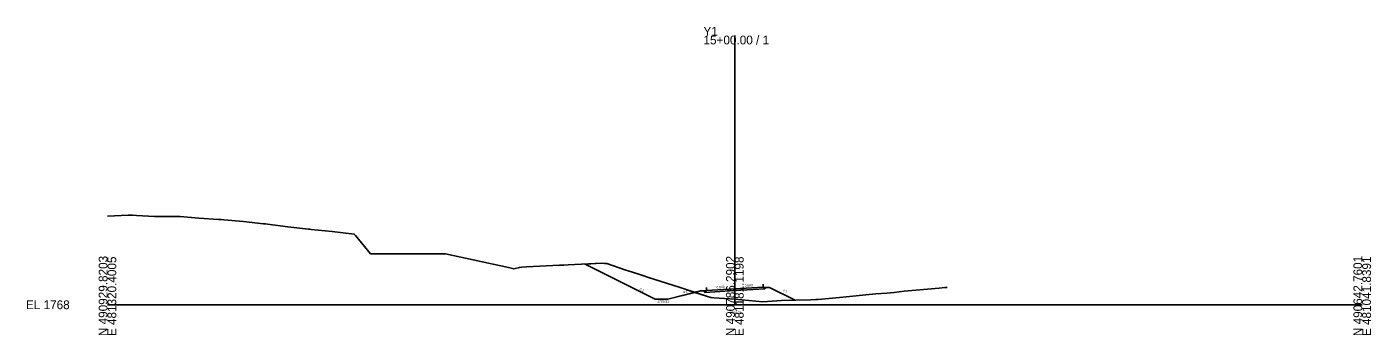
# Model space of a CAD drawing. Extents: x -26 to 403, y -10 to 6561.
# Drawn here: x -25.7 to 402.8, y 4990.3 to 5088.7 of the extents above; entities that cross this region are included whole.
import ezdxf

# ---------------------------------------------------------------- set-up
doc = ezdxf.new("R2010")
doc.units = 0
for name, color, linetype in [('Exist Cross Section Cell', 7, 'Continuous'), ('Exist XS Center Line Elevation Label', 7, 'Continuous'), ('Exist XS Ground Line', 7, 'Continuous'), ('Prop Road Sect_ Boring - Header (ID Tx)', 7, 'Continuous'), ('Prop Road Sect_ Material - Tx (Composite Desc)', 7, 'Continuous'), ('Prop XS Ditch Slope Text', 7, 'Continuous'), ('Prop XS Ditch Standard Text', 7, 'Continuous'), ('Prop XS EOT Tick Mark', 7, 'Continuous'), ('Prop XS Finish Grade', 7, 'Continuous'), ('Prop XS Finish Grade Earthwork', 7, 'Continuous'), ('Prop XS Finish Grade Pavement', 7, 'Continuous'), ('Prop XS Pvmt Edge Slope', 7, 'Continuous'), ('Prop XS SE Text', 7, 'Continuous'), ('Prop XS Side Slope Text', 7, 'Continuous'), ('Prop XS Subgrade Earthwork', 7, 'Continuous')]:
    doc.layers.add(name, color=color, linetype=linetype)

msp = doc.modelspace()

# ---------------------------------------------------------------- linework, layer by layer
at = {"layer": 'Exist Cross Section Cell'}
for p, q in [((200, 5000), (200, 5085.91)), ((0, 5000), (200, 5000)), ((200, 5000), (400, 5000))]:
    msp.add_line(p, q, dxfattribs=at)
at = {"layer": 'Exist XS Ground Line'}
msp.add_lwpolyline([(0, 5028.25), (6.64, 5028.64), (7.94, 5028.58), (9.2, 5028.51), (15.01, 5028.19), (21, 5028.23), (22.09, 5028.22), (23.14, 5028.15), (29.16, 5027.68), (35.36, 5027.27), (36.23, 5027.22), (37.08, 5027.14), (43.31, 5026.58), (49.73, 5025.85), (50.38, 5025.79), (51.01, 5025.69), (57.45, 5024.87), (64.09, 5024.15), (64.53, 5024.1), (64.95, 5024.06), (71.6, 5023.34), (78.67, 5022.57), (79.05, 5022.07), (83.89, 5016.31), (106.01, 5016.27), (107.73, 5016.27), (127.87, 5011.87), (129.51, 5011.43), (131.31, 5011.92), (132.12, 5011.97), (133.53, 5012.09), (144.09, 5012.65), (145.53, 5012.69), (146.9, 5012.72), (157.64, 5013.23), (158.49, 5013.21), (159.22, 5013.2), (165.23, 5011.1), (165.95, 5010.87), (167.66, 5010.31), (169.44, 5009.73), (170.66, 5009.34), (172.48, 5008.75), (182.26, 5005.58), (190.93, 5002.78), (192.35, 5002.32), (193.26, 5002.26), (198.38, 5001.92), (200, 5001.76), (208.91, 5000.92), (214.9, 5001.32), (224.17, 5001.56), (225.84, 5001.68), (226.58, 5001.72), (233.38, 5002.35), (244.99, 5003.45), (248.43, 5003.68), (250.8, 5003.9), (253.95, 5004.3), (265.16, 5005.27), (266.97, 5005.47), (267.74, 5005.56)], dxfattribs=at)
at = {"layer": 'Prop Road Sect_ Boring - Header (ID Tx)'}
for points in [[(209, 5005.6), (209.98, 5005.56), (209.51, 5005.09)], [(191, 5004.52), (190.42, 5003.95), (189.91, 5004.46)]]:
    msp.add_lwpolyline(points, close=True, dxfattribs=at)
at = {"layer": 'Prop Road Sect_ Material - Tx (Composite Desc)'}
for points in [[(170.66, 5009.34), (172.48, 5008.75), (182.26, 5005.58), (187.25, 5003.97), (178.62, 5001.81), (174.62, 5001.81), (152.29, 5012.97), (157.64, 5013.23), (158.49, 5013.21), (159.22, 5013.2), (165.23, 5011.1), (165.95, 5010.87), (167.66, 5010.31), (169.44, 5009.73)], [(211, 5005.52), (219.18, 5001.43), (214.9, 5001.32), (208.91, 5000.92), (200, 5001.76), (198.38, 5001.92), (193.26, 5002.26), (192.35, 5002.32), (190.93, 5002.78), (187.25, 5003.97), (189, 5004.4), (189.91, 5004.46), (190.42, 5003.95), (200.03, 5004.52), (209.51, 5005.09), (209.98, 5005.56)]]:
    msp.add_lwpolyline(points, close=True, dxfattribs=at)
at = {"layer": 'Prop XS EOT Tick Mark'}
for p, q in [((191, 5004.52), (191, 5005.52)), ((209, 5005.6), (209, 5006.6))]:
    msp.add_line(p, q, dxfattribs=at)
at = {"layer": 'Prop XS Finish Grade'}
for p, q in [((209, 5005.6), (209.98, 5005.56)), ((191, 5004.52), (189.91, 5004.46))]:
    msp.add_line(p, q, dxfattribs=at)
at = {"layer": 'Prop XS Finish Grade Earthwork'}
for p, q in [((174.62, 5001.81), (152.29, 5012.97)), ((209.98, 5005.56), (211, 5005.52)), ((211, 5005.52), (219.18, 5001.43)), ((178.62, 5001.81), (174.62, 5001.81)), ((189, 5004.4), (178.62, 5001.81)), ((189, 5004.4), (189.91, 5004.46))]:
    msp.add_line(p, q, dxfattribs=at)
at = {"layer": 'Prop XS Finish Grade Pavement'}
for p, q in [((200, 5005.06), (209, 5005.6)), ((191, 5004.52), (200, 5005.06))]:
    msp.add_line(p, q, dxfattribs=at)
at = {"layer": 'Prop XS Pvmt Edge Slope'}
for p, q in [((209, 5005.6), (209.51, 5005.09)), ((191, 5004.52), (190.42, 5003.95))]:
    msp.add_line(p, q, dxfattribs=at)
at = {"layer": 'Prop XS Subgrade Earthwork'}
for p, q in [((209.98, 5005.56), (209.51, 5005.09)), ((190.42, 5003.95), (189.91, 5004.46)), ((190.42, 5003.95), (200.03, 5004.52)), ((200.03, 5004.52), (209.51, 5005.09))]:
    msp.add_line(p, q, dxfattribs=at)

# ---------------------------------------------------------------- texts
at = {"layer": 'Exist Cross Section Cell'}
for s, p in [('Y1', (190, 5085.91)), ('15+00.00 / 1', (190, 5083.11)), ('EL 1768', (-26, 4998.6))]:
    msp.add_text(s, height=2.8, dxfattribs=at).set_placement(p)
for s, p in [('N 490929.8203', (0, 4990)), ('E 481320.4005', (2.8, 4990)), ('N 490786.2902', (200, 4990)), ('E 481181.1198', (202.8, 4990)), ('N 490642.7601', (400, 4990)), ('E 481041.8391', (402.8, 4990))]:
    msp.add_text(s, height=2.8, rotation=90, dxfattribs=at).set_placement(p)
at = {"layer": 'Exist XS Center Line Elevation Label'}
msp.add_text('1769.76', height=0.75, dxfattribs=at).set_placement((198.39, 4997.04))
at = {"layer": 'Prop XS Ditch Slope Text'}
msp.add_text('4:1', height=0.75, rotation=14.0362, dxfattribs=at).set_placement((183.6, 5003.62))
at = {"layer": 'Prop XS Ditch Standard Text'}
msp.add_text('1769.81', height=0.75, dxfattribs=at).set_placement((175.25, 5000.66))
at = {"layer": 'Prop XS SE Text'}
for p in [(194.17, 5005.21), (203.17, 5005.75)]:
    msp.add_text('0.060', height=0.75, rotation=3.4336, dxfattribs=at).set_placement(p)
at = {"layer": 'Prop XS Side Slope Text'}
for p in [(169.55, 5004.79), (215.22, 5004.39)]:
    msp.add_text('2:1', height=0.75, rotation=333.4349, dxfattribs=at).set_placement(p)

doc.saveas('drawing.dxf')
